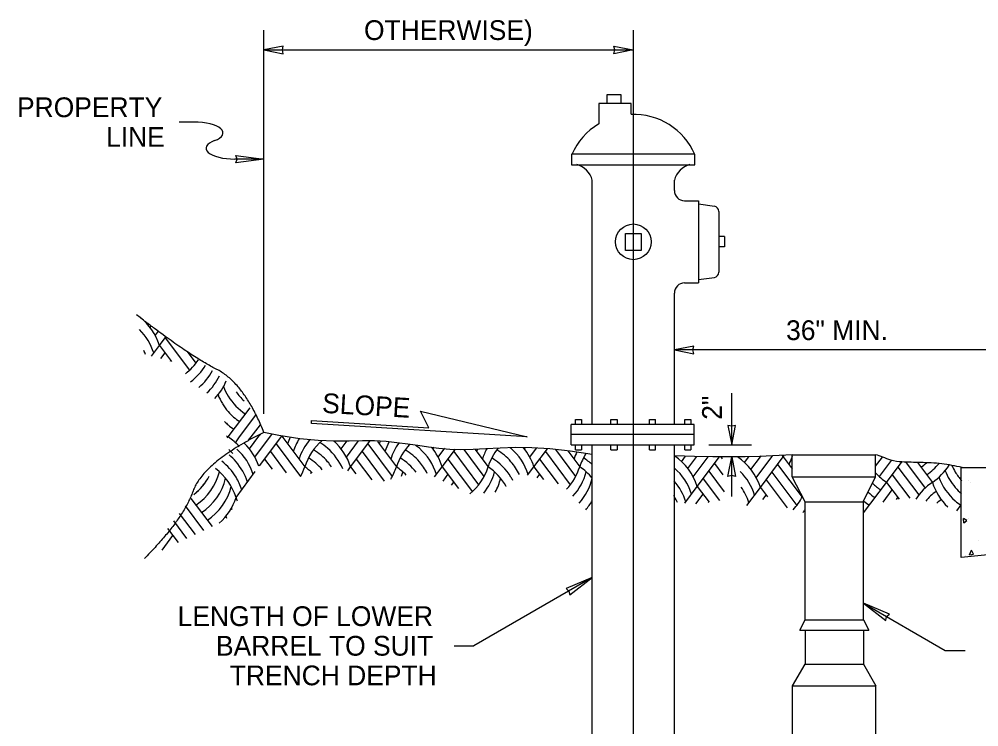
# Model space of a CAD drawing. Extents: x 99862 to 103151, y 100000 to 102076.
# Drawn here: x 101325 to 102102, y 100574 to 101147 of the extents above; entities that cross this region are included whole.
import ezdxf

# ---------------------------------------------------------------- set-up
doc = ezdxf.new("R2010")
doc.units = 0
for name, color, linetype in [('Level 10', 7, 'Continuous'), ('Level 14', 7, 'Continuous'), ('Level 15', 7, 'Continuous'), ('Level 17', 7, 'Continuous'), ('Level 18', 7, 'Continuous'), ('Level 2', 7, 'Continuous'), ('Level 20', 7, 'Continuous'), ('Level 3', 7, 'Continuous'), ('Level 6', 7, 'Continuous'), ('Level 8', 7, 'Continuous')]:
    doc.layers.add(name, color=color, linetype=linetype)

msp = doc.modelspace()

# ---------------------------------------------------------------- linework, layer by layer
at = {"layer": 'Level 10'}
for p, q in [((102094.18, 100773.45), (102094.18, 100773.45)), ((102095.48, 100772.1), (102095.48, 100772.1)), ((102090.16, 100739.13), (102089.64, 100742.83)), ((102092.54, 100740.98), (102089.64, 100742.83)), ((102090.16, 100739.13), (102092.54, 100740.98)), ((102094.18, 100742.58), (102094.18, 100742.58)), ((102089.64, 100738.32), (102089.64, 100738.32)), ((102101.6, 100725.28), (102101.6, 100725.28)), ((102091.78, 100713.05), (102091.78, 100713.05)), ((102094.66, 100713.28), (102096.3, 100717.05)), ((102094.66, 100713.28), (102097.85, 100713.87)), ((102097.85, 100713.87), (102096.3, 100717.05))]:
    msp.add_line(p, q, dxfattribs=at)
at = {"layer": 'Level 14'}
for p, q in [((101466.38, 101063.87), (101454.38, 101063.87)), ((101523.11, 101033.87), (101499.68, 101033.87))]:
    msp.add_line(p, q, dxfattribs=at)
msp.add_lwpolyline([(101523.11, 101033.87), (101500.29, 101030.89), (101501.34, 101033.87), (101500.28, 101036.86)], close=True, dxfattribs=at)
for centre, start_param, end_param in [((101466.55, 101055.09), 5.497747, 7.861127), ((101499.68, 101042.66), 2.356226, 4.712389)]:
    msp.add_ellipse(centre, major_axis=(23.43, 0), ratio=0.375, start_param=start_param, end_param=end_param, dxfattribs=at)
at = {"layer": 'Level 15'}
for p, q in [((101523.11, 100827.52), (101523.11, 101138.38)), ((101822.33, 101138.38), (101822.33, 100280.71)), ((101523.11, 101122.38), (101822.33, 101122.38)), ((102119.13, 100879.28), (101855.6, 100879.28)), ((101902.04, 100802.41), (101902.04, 100844.39)), ((101883.54, 100802.41), (101918.04, 100802.41)), ((101902.04, 100760.6), (101902.04, 100792.6)), ((102008.66, 100674.15), (102074.98, 100635.86)), ((101677.09, 100639.6), (101693.09, 100639.6)), ((102074.98, 100635.86), (102090.98, 100635.86))]:
    msp.add_line(p, q, dxfattribs=at)
for points in [[(101523.11, 101122.38), (101538.84, 101119.3), (101538.11, 101122.38), (101538.84, 101125.47)], [(101822.33, 101122.38), (101806.6, 101119.3), (101807.33, 101122.38), (101806.6, 101125.47)], [(101855.6, 100879.28), (101871.33, 100876.2), (101870.6, 100879.28), (101871.33, 100882.37)], [(101902.04, 100802.41), (101905.12, 100818.13), (101902.04, 100817.41), (101898.96, 100818.13)], [(101902.04, 100792.6), (101905.12, 100776.87), (101902.04, 100777.6), (101898.96, 100776.87)], [(101789.08, 100694.87), (101767.81, 100686.04), (101770.22, 100683.98), (101770.8, 100680.87)], [(102008.66, 100674.15), (102026.94, 100660.15), (102027.52, 100663.26), (102029.93, 100665.32)]]:
    msp.add_lwpolyline(points, close=True, dxfattribs=at)
msp.add_lwpolyline([(101789.08, 100694.87), (101693.09, 100639.6)], dxfattribs=at)
at = {"layer": 'Level 17'}
msp.add_lwpolyline([(102259.55, 100727.93), (102251.04, 100727.41), (102087.79, 100711.2), (102087.79, 100784.08), (102119.13, 100784.08), (102119.13, 100749.48), (102248.94, 100762.81), (102249.23, 100762.81)], dxfattribs=at)
at = {"layer": 'Level 18'}
for p, q in [((101820.48, 101079.01), (101794.41, 101079.01)), ((101794.41, 101079.01), (101794.41, 101062.53)), ((101820.48, 101070.25), (101820.48, 101079.01)), ((101789.08, 100818.9), (101789.08, 101016.78)), ((101855.6, 101008.55), (101855.6, 101016.78)), ((101863.8, 101000.03), (101875.03, 101000.03)), ((101875.03, 101000.03), (101875.03, 100933.52)), ((101875.03, 100997.63), (101888.04, 100995.78)), ((101891.49, 100991.52), (101891.49, 100942.31)), ((101896.3, 100971.05), (101891.49, 100971.05)), ((101896.3, 100971.05), (101896.3, 100962.81)), ((101896.3, 100962.81), (101891.49, 100962.81)), ((101875.03, 100936.21), (101888.04, 100938.06)), ((101863.8, 100933.52), (101875.03, 100933.52)), ((101855.6, 100818.9), (101855.6, 100925.28)), ((101871.54, 100818.9), (101772.06, 100818.9)), ((101772.06, 100802.41), (101772.06, 100818.9)), ((101775.43, 100822.97), (101780.39, 100822.97)), ((101775.43, 100818.9), (101775.43, 100822.97)), ((101780.39, 100822.97), (101780.39, 100818.9)), ((101804.23, 100822.95), (101809.19, 100822.95)), ((101804.23, 100818.9), (101804.23, 100822.95)), ((101809.19, 100822.95), (101809.19, 100818.9)), ((101835.4, 100822.97), (101840.36, 100822.97)), ((101835.4, 100818.9), (101835.4, 100822.97)), ((101840.36, 100818.9), (101840.36, 100822.97)), ((101863.99, 100822.91), (101868.91, 100822.91)), ((101863.99, 100818.9), (101863.99, 100822.91)), ((101868.91, 100822.91), (101868.91, 100818.9)), ((101871.54, 100802.41), (101871.54, 100818.9)), ((101871.54, 100810.67), (101772.06, 100810.67)), ((101772.06, 100802.41), (101871.54, 100802.41)), ((101775.43, 100798.31), (101775.43, 100802.41)), ((101775.43, 100798.31), (101780.39, 100798.31)), ((101780.39, 100802.41), (101780.39, 100798.31)), ((101804.23, 100798.31), (101804.23, 100802.41)), ((101804.23, 100798.31), (101809.19, 100798.31)), ((101809.19, 100802.41), (101809.19, 100798.31)), ((101835.4, 100798.33), (101835.4, 100802.41)), ((101835.4, 100798.33), (101840.36, 100798.33)), ((101840.36, 100798.33), (101840.36, 100802.41)), ((101863.99, 100798.27), (101863.99, 100802.41)), ((101863.99, 100798.27), (101868.91, 100798.27)), ((101868.91, 100802.41), (101868.91, 100798.27)), ((101951.06, 100776.6), (101951.06, 100794.42)), ((101951.06, 100794.42), (102018.6, 100794.42)), ((102018.6, 100776.6), (102018.6, 100794.42)), ((101961.39, 100756.12), (101951.06, 100776.6)), ((101951.06, 100776.6), (102018.6, 100776.6)), ((102008.48, 100756.12), (102018.6, 100776.6)), ((101961.39, 100756.12), (102008.48, 100756.12)), ((101961.58, 100660.56), (101961.58, 100756.12)), ((102008.66, 100660.56), (102008.66, 100756.12)), ((101957.08, 100652.3), (101961.58, 100660.56)), ((101961.58, 100660.56), (102008.66, 100660.56)), ((102008.66, 100660.56), (102013.2, 100652.3)), ((101957.08, 100652.3), (102013.2, 100652.3)), ((101961.58, 100652.3), (101961.58, 100624.63)), ((102008.66, 100652.3), (102008.66, 100624.63)), ((101951.21, 100607.08), (101961.58, 100624.63)), ((101961.58, 100624.63), (102008.66, 100624.63)), ((102008.66, 100624.63), (102018.78, 100607.08)), ((101951.21, 100551.77), (101951.21, 100607.08)), ((101951.21, 100607.08), (102018.78, 100607.08)), ((102018.78, 100551.77), (102018.78, 100607.08))]:
    msp.add_line(p, q, dxfattribs=at)
msp.add_lwpolyline([(101801.05, 101079.01), (101801.05, 101086.22), (101812.24, 101086.22), (101812.24, 101079.01)], dxfattribs=at)
for points in [[(101872.06, 101029.27), (101872.06, 101037.77), (101772.34, 101037.77), (101772.34, 101029.27)], [(101815.94, 100959.86), (101815.94, 100973.7), (101828.7, 100973.7), (101828.7, 100959.86)]]:
    msp.add_lwpolyline(points, close=True, dxfattribs=at)
msp.add_circle((101822.34, 100966.86), 14.47, dxfattribs=at)
for centre, radius, start, end in [((101822.34, 101015.63), 54.54, 23.89556, 91.97586), ((101822.34, 101015.63), 54.54, 120.92859, 156.10444), ((101772.15, 101012.5), 17.46, 14.112, 75.60063), ((101872.52, 101012.5), 17.46, 104.39937, 165.888), ((101863.89, 101008.42), 8.31, 180, 270), ((101887.43, 100991.54), 4.16, 0, 81.50484), ((101887.43, 100942.18), 4.16, 278.49516, 0), ((101863.89, 100925.3), 8.31, 90, 180)]:
    msp.add_arc(centre, radius, start, end, dxfattribs=at)
at = {"layer": 'Level 2'}
for p, q in [((101425.76, 100903.13), (101425.94, 100903.37)), ((101430.85, 100897.55), (101431.94, 100899)), ((101435.16, 100890.92), (101437.94, 100894.63)), ((101438.5, 100883), (101443.94, 100890.26)), ((101443.14, 100889.19), (101462.88, 100862.87)), ((101432, 100874.33), (101438.5, 100883)), ((101438.5, 100883), (101448.35, 100869.87)), ((101439.7, 100872.23), (101443.14, 100876.81)), ((101460.87, 100877.92), (101467.98, 100868.45)), ((101447.41, 100870.13), (101447.78, 100870.62)), ((101501.83, 100843.7), (101501.93, 100843.84)), ((101506.93, 100838.12), (101506.94, 100838.13)), ((101494.18, 100808.75), (101511.91, 100832.39)), ((101503.46, 100808.75), (101516.65, 100826.33)), ((101512.75, 100808.75), (101520.22, 100818.71)), ((101528.35, 100809.32), (101529.69, 100811.1)), ((101500, 100804.13), (101503.46, 100808.75)), ((101510.72, 100806.05), (101512.75, 100808.75)), ((101511.42, 100799.12), (101519.07, 100809.32)), ((101515.73, 100792.49), (101528.35, 100809.32)), ((101519.07, 100809.32), (101520.25, 100810.88)), ((101519.65, 100785.34), (101537.63, 100809.32)), ((101537.29, 100809.78), (101537.63, 100809.32)), ((101537.63, 100809.32), (101556.19, 100784.57)), ((101580.57, 100804.7), (101581.25, 100805.61)), ((101585.67, 100799.12), (101590.53, 100805.61)), ((101589.97, 100792.49), (101599.82, 100805.61)), ((101593.32, 100784.57), (101608.89, 100805.34)), ((101615.07, 100805.06), (101630.44, 100784.57)), ((101528.35, 100796.94), (101541.27, 100779.72)), ((101532.99, 100803.13), (101552.8, 100776.72)), ((101602.6, 100796.94), (101620.52, 100773.05)), ((101607.24, 100803.13), (101627.1, 100776.65)), ((101659.91, 100799.12), (101660.88, 100800.41)), ((101664.22, 100792.49), (101669.56, 100799.61)), ((101667.56, 100784.57), (101678.24, 100798.81)), ((101676.84, 100796.94), (101697.04, 100770.02)), ((101684.96, 100798.49), (101701.34, 100776.65)), ((101693.96, 100798.86), (101704.68, 100784.57)), ((101734.16, 100799.12), (101734.83, 100800.02)), ((101738.46, 100792.49), (101743.91, 100799.74)), ((101741.81, 100784.57), (101752.73, 100799.13)), ((101751.09, 100796.94), (101771.28, 100770.02)), ((101759.19, 100798.51), (101775.59, 100776.65)), ((101769.2, 100797.55), (101778.93, 100784.57)), ((101523.71, 100790.76), (101529.74, 100782.72)), ((101597.96, 100790.76), (101610.45, 100774.09)), ((101672.2, 100790.76), (101691.94, 100764.44)), ((101746.45, 100790.76), (101761.33, 100770.92)), ((101861.42, 100788.75), (101864.67, 100793.09)), ((101866.52, 100783.18), (101873.78, 100792.86)), ((101870.82, 100776.54), (101882.93, 100792.69)), ((101874.16, 100768.62), (101892.15, 100792.61)), ((101893.3, 100792.6), (101894.42, 100791.11)), ((101912.48, 100787.98), (101915.94, 100792.6)), ((101915.94, 100792.6), (101916.23, 100792.99)), ((101917.57, 100782.4), (101925.22, 100792.6)), ((101921.88, 100775.77), (101934.5, 100792.6)), ((101925.22, 100792.6), (101925.81, 100793.38)), ((101925.22, 100767.85), (101943.78, 100792.6)), ((101934.5, 100792.6), (101935.39, 100793.78)), ((101942.67, 100794.08), (101943.78, 100792.6)), ((101943.78, 100792.6), (101951.06, 100782.89)), ((102018.6, 100785), (102024.17, 100792.42)), ((102021.6, 100776.62), (102031.4, 100789.68)), ((102027.42, 100772), (102040.02, 100788.81)), ((102042.72, 100788.71), (102058.72, 100767.39)), ((102052.42, 100788.16), (102064.54, 100772)), ((101500.51, 100759.82), (101516.15, 100780.68)), ((101590.97, 100781.44), (101593.32, 100784.57)), ((101593.32, 100784.57), (101597.51, 100778.98)), ((101661.4, 100776.36), (101667.56, 100784.57)), ((101667.56, 100784.57), (101680.71, 100767.04)), ((101736.73, 100777.8), (101741.81, 100784.57)), ((101741.81, 100784.57), (101749.58, 100774.21)), ((101883.44, 100781), (101896.04, 100764.21)), ((101888.08, 100787.19), (101894.85, 100778.16)), ((101934.5, 100780.22), (101954.69, 100753.3)), ((101939.14, 100786.41), (101959, 100759.93)), ((102036.7, 100784.38), (102053.62, 100761.81)), ((101478.54, 100776.74), (101478.61, 100776.65)), ((101668.22, 100773.07), (101672.2, 100778.38)), ((101675.03, 100769.78), (101676.84, 100772.19)), ((101744.4, 100775.65), (101746.45, 100778.38)), ((101878.8, 100774.81), (101892.03, 100757.18)), ((101929.86, 100774.04), (101946.93, 100751.27)), ((102032.06, 100778.19), (102046.36, 100759.13)), ((101468.76, 100765.03), (101469.2, 100764.44)), ((101473.62, 100770.92), (101474.3, 100770.02)), ((101864.04, 100755.13), (101874.16, 100768.62)), ((101874.16, 100768.62), (101883.75, 100755.84)), ((101914.33, 100753.32), (101925.22, 100767.85)), ((101925.22, 100767.85), (101930.97, 100760.18)), ((102008.86, 100747.25), (102027.42, 100772)), ((102024.73, 100756.05), (102032.06, 100765.82)), ((102027.42, 100772), (102037.73, 100758.25)), ((101464.04, 100758.96), (101481.1, 100736.2)), ((101872.87, 100754.52), (101878.8, 100762.44)), ((101927.17, 100758.07), (101929.86, 100761.66)), ((102035.49, 100758.02), (102036.7, 100759.63)), ((101459.31, 100752.88), (101474.25, 100732.97)), ((101883.05, 100755.72), (101883.44, 100756.25)), ((102084.43, 100749.02), (102087.92, 100753.68)), ((101454.59, 100746.8), (101467.39, 100729.73)), ((101445.15, 100734.64), (101453.68, 100723.26)), ((101449.87, 100740.72), (101460.54, 100726.5)), ((101440.63, 100717.1), (101449.47, 100728.88))]:
    msp.add_line(p, q, dxfattribs=at)
for centre, start, end in [((101393.74, 100868.76), 56.09535, 56.09634), ((101393.74, 100868.76), 56.08425, 56.09535), ((101393.74, 100868.76), 17.6434, 51.75329), ((101389.1, 100862.57), 17.6434, 44.93638), ((101384.46, 100856.39), 24.14971, 28.43402), ((101430.86, 100897.24), 307.55806, 326.43655), ((101435.5, 100891.05), 306.83176, 329.20914), ((101440.14, 100884.86), 310.01548, 331.83917), ((101444.78, 100878.67), 313.15031, 334.43121), ((101449.42, 100872.49), 316.24748, 337.04822), ((101529.67, 100860.11), 201.43438, 211.11957), ((101534.31, 100866.3), 200.87781, 211.33197), ((101538.95, 100872.49), 215.27668, 227.20355), ((101529.67, 100860.11), 211.36516, 220.94161), ((101534.31, 100866.3), 211.33188, 236.09639), ((101529.67, 100860.11), 220.94154, 236.09639), ((101525.03, 100853.92), 224.12628, 228.95992), ((101525.02, 100853.92), 228.95986, 236.09639), ((101520.39, 100847.74), 234.15274, 236.09639), ((101520.39, 100769.77), 123.90361, 125.44007), ((101467.98, 100769.77), 41.51201, 56.09634), ((101474.31, 100770.33), 18.35813, 45.07934), ((101582.39, 100795.08), 161.86969, 162.3566), ((101587.03, 100788.89), 155.26186, 162.3566), ((101591.67, 100782.71), 148.44352, 162.3566), ((101596.32, 100776.52), 140.1689, 162.3566), ((101600.96, 100770.33), 130.84642, 162.3566), ((101543.91, 100764.14), 48.95968, 58.54646), ((101548.55, 100770.33), 17.6434, 48.68118), ((101661.28, 100788.89), 159.98822, 162.3566), ((101665.92, 100782.71), 152.16202, 162.3566), ((101670.56, 100776.52), 144.51205, 162.3566), ((101463.34, 100763.58), 42.5792, 48.06228), ((101469.67, 100764.14), 17.6434, 47.9305), ((101539.27, 100757.96), 40.94134, 59.30215), ((101543.91, 100764.14), 23.61782, 48.95975), ((101675.2, 100770.33), 136.52962, 162.3566), ((101613.52, 100757.96), 40.94134, 59.30215), ((101618.16, 100764.14), 48.95968, 53.7444), ((101618.16, 100764.14), 17.6434, 48.95975), ((101622.8, 100770.33), 17.6434, 40.1409), ((101740.16, 100782.71), 159.76574, 162.3566), ((101744.81, 100776.52), 151.03088, 162.3566), ((101749.45, 100770.33), 141.35369, 162.3566), ((101687.76, 100757.96), 40.94134, 59.30215), ((101692.4, 100764.14), 48.95968, 49.94708), ((101692.4, 100764.14), 17.6434, 48.95975), ((101697.04, 100770.33), 17.6434, 39.27011), ((101814.41, 100782.71), 161.6604, 162.3566), ((101819.05, 100776.52), 154.83962, 162.3566), ((101460.39, 100751.77), 31.33163, 52.57708), ((101465.03, 100757.96), 40.94134, 50.45234), ((101465.03, 100757.96), 17.6434, 40.94141), ((101534.63, 100751.77), 40.47662, 58.48737), ((101539.27, 100757.96), 34.71219, 40.94141), ((101608.88, 100751.77), 37.14403, 58.48737), ((101613.52, 100757.96), 26.98331, 40.94141), ((101683.12, 100751.77), 31.33163, 58.48737), ((101687.76, 100757.96), 25.76242, 40.94141), ((101823.69, 100770.33), 147.90308, 162.3566), ((101757.37, 100751.77), 47.58354, 58.48737), ((101881.8, 100754.39), 123.90361, 123.90451), ((101829.4, 100754.39), 56.09551, 56.09634), ((101829.4, 100754.39), 17.6434, 56.09551), ((101880.46, 100753.61), 56.09536, 56.09634), ((101880.46, 100753.61), 17.6434, 56.09536), ((101988.54, 100778.36), 160.36493, 162.3566), ((101993.18, 100772.17), 154.22654, 162.3566), ((101993.18, 100772.17), 153.72579, 154.2266), ((102044.8, 100755.44), 123.90393, 123.90463), ((102029.06, 100823.36), 303.90361, 310.82747), ((101441.83, 100792.62), 303.90361, 345.01126), ((101455.75, 100745.58), 17.6434, 53.11513), ((101511.43, 100798.81), 331.92959, 342.3566), ((101529.99, 100745.58), 46.49224, 56.09639), ((101516.07, 100792.62), 343.46672, 345.01126), ((101585.68, 100798.81), 328.87171, 342.3566), ((101604.24, 100745.58), 43.52341, 56.09639), ((101590.32, 100792.62), 340.46444, 345.01126), ((101659.92, 100798.81), 309.61014, 342.3566), ((101664.56, 100792.62), 321.35053, 345.01126), ((101678.48, 100745.58), 29.36293, 56.09639), ((101734.17, 100798.81), 316.5026, 342.3566), ((101738.81, 100792.62), 317.45488, 345.01126), ((101752.73, 100745.58), 39.4164, 56.09639), ((101824.76, 100748.2), 48.95968, 49.27025), ((101824.76, 100748.2), 17.6434, 48.95975), ((101875.82, 100747.42), 17.6434, 45.06433), ((102033.7, 100817.18), 303.90361, 320.60965), ((102038.34, 100810.99), 303.90361, 327.75148), ((102118.58, 100798.61), 201.43438, 220.94161), ((102123.22, 100804.8), 204.25889, 211.33197), ((102123.22, 100804.8), 211.33188, 222.03912), ((101437.19, 100798.81), 308.53107, 332.49969), ((101446.47, 100786.43), 303.90361, 346.31988), ((101460.39, 100751.77), 17.6434, 31.33172), ((101669.2, 100786.43), 331.54858, 346.31988), ((101683.12, 100751.77), 27.56971, 31.33172), ((101743.45, 100786.43), 318.40849, 345.95566), ((101820.12, 100742.01), 40.94134, 41.68711), ((101820.12, 100742.01), 17.6434, 40.94141), ((102053.62, 100810.99), 221.8026, 236.09639), ((102113.94, 100792.43), 200.24322, 228.95992), ((101451.11, 100780.24), 303.90361, 345.77133), ((101673.84, 100780.24), 345.56367, 345.77133), ((101871.18, 100741.24), 17.6434, 35.02567), ((102048.98, 100804.8), 225.47301, 236.09639), ((102090.74, 100733.02), 123.90361, 147.47509), ((102095.38, 100726.83), 126.30625, 140.45867), ((102109.3, 100786.24), 197.6434, 226.73884), ((102118.58, 100798.61), 220.94154, 229.56065), ((101455.75, 100774.06), 311.68299, 342.3566), ((101545.27, 100774.06), 197.64354, 201.39049), ((101748.09, 100780.24), 319.36371, 330.46941), ((101815.48, 100735.83), 31.33163, 32.80985), ((101815.48, 100735.83), 24.81791, 31.33172), ((101917.58, 100782.09), 316.63377, 332.68399), ((102039.7, 100792.43), 229.2269, 236.09639), ((102044.34, 100798.61), 227.35922, 236.09639), ((102100.02, 100720.64), 127.1006, 132.93339), ((102113.94, 100792.43), 228.95986, 236.09639), ((101540.63, 100767.87), 200.87781, 202.46481), ((101922.22, 100775.9), 322.75071, 326.73573), ((102104.66, 100714.46), 126.331, 126.528), ((101535.99, 100761.68), 201.43438, 203.52627), ((101752.73, 100774.06), 320.32081, 320.39121), ((102035.06, 100786.24), 236.09549, 236.09602), ((101531.35, 100755.49), 200.24322, 200.38305)]:
    msp.add_arc(centre, 46.97, start, end, dxfattribs=at)
at = {"layer": 'Level 3'}
msp.add_lwpolyline([(101561.77, 100822.2), (101656.56, 100816.28), (101649.91, 100829.68), (101736.28, 100808.82), (101561.62, 100819.73)], close=True, dxfattribs=at)
at = {"layer": 'Level 6'}
for p, q in [((101789.08, 100511.98), (101789.08, 100802.41)), ((101855.6, 100511.98), (101855.6, 100802.41))]:
    msp.add_line(p, q, dxfattribs=at)
at = {"layer": 'Level 8'}
for points in [[(101789.08, 100794.45), (101771.26, 100797.35), (101754.79, 100799.23), (101740.14, 100800.03), (101726.58, 100800.27), (101714.36, 100799.75), (101702.93, 100799.23), (101692.54, 100798.71), (101682.7, 100798.4), (101673.66, 100798.71), (101664.88, 100799.47), (101656.36, 100800.56), (101647.85, 100801.88), (101639.61, 100802.96), (101630.83, 100804.01), (101622.08, 100805.08), (101612.73, 100805.61), (101602.93, 100805.61), (101592.29, 100805.36), (101580.33, 100805.36), (101567, 100805.86), (101552.1, 100807.21), (101535.09, 100809.87), (101523.11, 100812.52)], [(101951.06, 100794.42), (101924.73, 100792.85), (101913.04, 100792.6), (101900.28, 100792.6), (101886.71, 100792.6), (101871.81, 100792.85), (101855.6, 100793.37)]]:
    msp.add_lwpolyline(points, dxfattribs=at)
for points in [[(101523.11, 100812.52), (101507.18, 100852.42), (101461.98, 100875), (101419.94, 100907.75)], [(101523.11, 100812.52), (101474, 100788.07), (101457.25, 100741.38), (101426.26, 100710.32)]]:
    msp.add_open_spline(points, degree=2, dxfattribs=at)
msp.add_spline([(102088.56, 100784.08), (102072.13, 100787.05), (102054.99, 100788.03), (102039.9, 100788.56), (102030.99, 100789.86), (102024.49, 100792.45), (102018.6, 100794.42)], degree=3, dxfattribs=at)

# ---------------------------------------------------------------- texts
at = {"layer": 'Level 20'}
for s, p in [('OTHERWISE)', (101604.2, 101130.38)), ('PROPERTY', (101323.14, 101067.87)), ('LINE', (101395.28, 101043.87)), ('36" MIN.', (101946.07, 100887.28)), ('LENGTH OF LOWER', (101453.25, 100655.6)), ('BARREL TO SUIT', (101484.28, 100631.6)), ('TRENCH DEPTH', (101495.47, 100607.6))]:
    msp.add_text(s, height=16, dxfattribs=at).set_placement(p)
for s, rotation, p in [('SLOPE', 356.67688, (101569.97, 100828.4)), ('2"', 90, (101894.04, 100822.7))]:
    msp.add_text(s, height=16, rotation=rotation, dxfattribs=at).set_placement(p)

doc.saveas('drawing.dxf')
